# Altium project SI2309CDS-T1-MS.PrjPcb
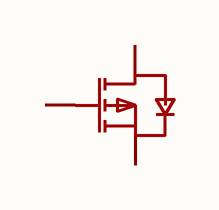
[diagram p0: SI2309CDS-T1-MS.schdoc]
1 sheet, 1 parts. Net scope: global (net labels, ports and power ports of the same name join across sheets).

## Sheet SI2309CDS-T1-MS.schdoc
size 127 x 101 mm

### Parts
Q?  si2309cds-t1-ms  [SOT-23-3_L2.9-W1.3-P1.90-LS2.4-BR]  (value not drawn)

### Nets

Not connected (* = marked no-connect by the designer): Q? 1(G) 2(S) 3(D)

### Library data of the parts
Q? = si2309cds-t1-ms: 数量:1个P沟道;漏源电压(Vdss):60V;连续漏极电流(Id):2A;导通电阻(RDS(on)):200mΩ@4.5V;耗散功率(Pd):1.5W;阈值电压(Vgs(th)):2.6V;; Manufacturer: MSKSEMI(美森科); AddInBom: yes; ModelId: c62791f0466c4ae2a892c056b845b0ca; ModelName: SOT-23-3P_L2.9-W1.3-H1.0-LS2.4-P0.95; ModelTransform: 98.425,114.173,0,180,0,0,0.0005,-0.0005,0; Number: 1个P沟道; Drain to Source Voltage: 60V; Current - Continuous Drain(Id): 2A; Pd - Power Dissipation: 1.5W; Gate Threshold Voltage (Vgs(th)): 2.6V; Gate Charge(Qg): 11.3nC@30V; Input Capacitance(Ciss): 444.2pF; Reverse Transfer Capacitance (Crss@Vds): 17.9pF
